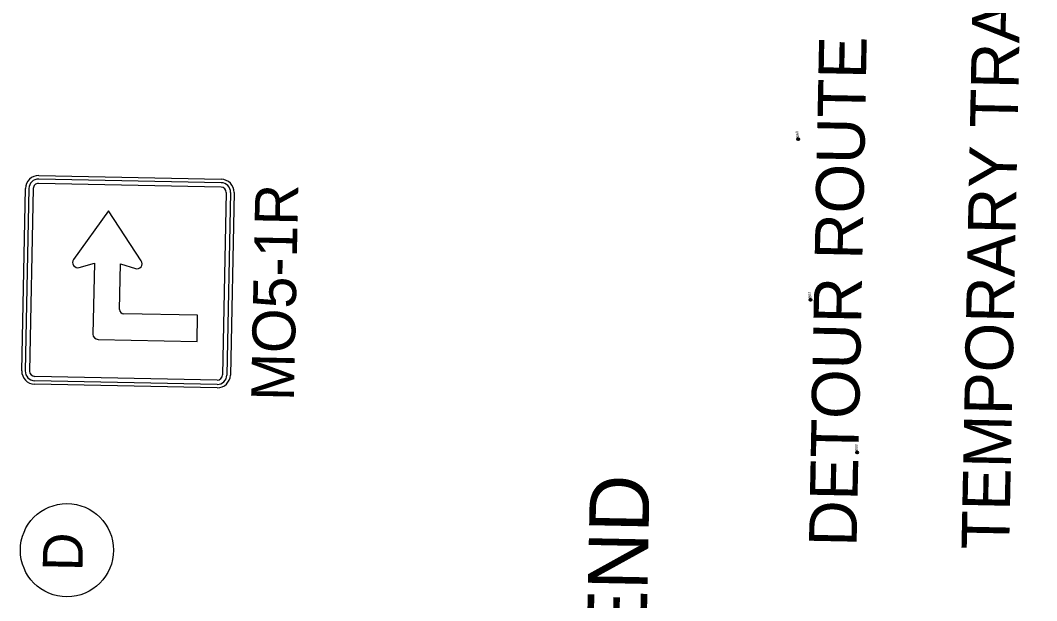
# Model space of a CAD drawing. Extents: x 335726 to 369746, y 119154 to 200788.
# Drawn here: x 356961 to 360798, y 160571 to 162762 of the extents above; entities that cross this region are included whole.
import ezdxf

# ---------------------------------------------------------------- set-up
doc = ezdxf.new("R2010")
doc.units = 0
for name, color, linetype in [('CA-TEXT', 7, 'Continuous'), ('E_SOIL_BORE1 [KAPUR_CADDS_LEVELS]', 7, 'Continuous'), ('E_SOIL_BORE2 [KAPUR_CADDS_LEVELS]', 7, 'Continuous'), ('P_MARK', 7, 'Continuous'), ('P_SGN_Cell', 7, 'Continuous')]:
    doc.layers.add(name, color=color, linetype=linetype)

msp = doc.modelspace()

# ---------------------------------------------------------------- linework, layer by layer
at = {"layer": 'CA-TEXT'}
msp.add_circle((357137.2, 160762), 175.9, dxfattribs=at)
at = {"layer": 'P_MARK'}
for p, q in [((359897.4, 162318.3), (359897.4, 162308.3)), ((359892.4, 162313.3), (359902.4, 162313.3)), ((359938.5, 161706.9), (359948.5, 161706.9)), ((359943.5, 161711.9), (359943.5, 161701.9)), ((360114.5, 161131), (360124.5, 161131)), ((360119.5, 161136), (360119.5, 161126))]:
    msp.add_line(p, q, dxfattribs=at)
for centre in [(359897.4, 162313.3), (359943.5, 161706.9), (360119.5, 161131)]:
    msp.add_circle(centre, 5, dxfattribs=at)
for centre, radius, start, end in [((359897.4, 162313.3), 4.5, 89.9869, 179.9869), ((359897.4, 162313.3), 4, 89.9869, 179.9869), ((359897.4, 162313.3), 3.5, 89.9869, 179.9869), ((359897.4, 162313.3), 3, 89.9869, 179.9869), ((359897.4, 162313.3), 2.5, 89.9869, 179.9869), ((359897.4, 162313.3), 2, 89.9869, 179.9869), ((359897.4, 162313.3), 1.5, 89.9869, 179.9869), ((359897.4, 162313.3), 1, 89.9869, 179.9869), ((359897.4, 162313.3), 0.5, 89.9869, 179.9869), ((359897.4, 162313.3), 4.5, 269.9869, 359.9869), ((359897.4, 162313.3), 4, 269.9869, 359.9869), ((359897.4, 162313.3), 3.5, 269.9869, 359.9869), ((359897.4, 162313.3), 3, 269.9869, 359.9869), ((359897.4, 162313.3), 2.5, 269.9869, 359.9869), ((359897.4, 162313.3), 2, 269.9869, 359.9869), ((359897.4, 162313.3), 1.5, 269.9869, 359.9869), ((359897.4, 162313.3), 1, 269.9869, 359.9869), ((359897.4, 162313.3), 0.5, 269.9869, 359.9869), ((359943.5, 161706.9), 4.5, 89.9869, 179.9869), ((359943.5, 161706.9), 4, 89.9869, 179.9869), ((359943.5, 161706.9), 3.5, 89.9869, 179.9869), ((359943.5, 161706.9), 3, 89.9869, 179.9869), ((359943.5, 161706.9), 2.5, 89.9869, 179.9869), ((359943.5, 161706.9), 2, 89.9869, 179.9869), ((359943.5, 161706.9), 1.5, 89.9869, 179.9869), ((359943.5, 161706.9), 1, 89.9869, 179.9869), ((359943.5, 161706.9), 0.5, 89.9869, 179.9869), ((359943.5, 161706.9), 4.5, 269.9869, 359.9869), ((359943.5, 161706.9), 4, 269.9869, 359.9869), ((359943.5, 161706.9), 3.5, 269.9869, 359.9869), ((359943.5, 161706.9), 3, 269.9869, 359.9869), ((359943.5, 161706.9), 2.5, 269.9869, 359.9869), ((359943.5, 161706.9), 2, 269.9869, 359.9869), ((359943.5, 161706.9), 1.5, 269.9869, 359.9869), ((359943.5, 161706.9), 1, 269.9869, 359.9869), ((359943.5, 161706.9), 0.5, 269.9869, 359.9869), ((360119.5, 161131), 4.5, 89.9869, 179.9869), ((360119.5, 161131), 4, 89.9869, 179.9869), ((360119.5, 161131), 3.5, 89.9869, 179.9869), ((360119.5, 161131), 3, 89.9869, 179.9869), ((360119.5, 161131), 2.5, 89.9869, 179.9869), ((360119.5, 161131), 2, 89.9869, 179.9869), ((360119.5, 161131), 1.5, 89.9869, 179.9869), ((360119.5, 161131), 1, 89.9869, 179.9869), ((360119.5, 161131), 0.5, 89.9869, 179.9869), ((360119.5, 161131), 4.5, 269.9869, 359.9869), ((360119.5, 161131), 4, 269.9869, 359.9869), ((360119.5, 161131), 3.5, 269.9869, 359.9869), ((360119.5, 161131), 3, 269.9869, 359.9869), ((360119.5, 161131), 2.5, 269.9869, 359.9869), ((360119.5, 161131), 2, 269.9869, 359.9869), ((360119.5, 161131), 1.5, 269.9869, 359.9869), ((360119.5, 161131), 1, 269.9869, 359.9869), ((360119.5, 161131), 0.5, 269.9869, 359.9869)]:
    msp.add_arc(centre, radius, start, end, dxfattribs=at)
at = {"layer": 'P_SGN_Cell'}
for p, q in [((357719.4, 162148.8), (357030.5, 162162.7)), ((357030.7, 162175.8), (357719.7, 162161.9)), ((356966.7, 161438.7), (356980.5, 162127.6)), ((356993.7, 162127.3), (356979.8, 161438.4)), ((357010.1, 162127), (356996.2, 161438.1)), ((357719.1, 162132.4), (357030.1, 162146.3)), ((357738.4, 162112.3), (357724.5, 161423.4)), ((357754.7, 162112), (357740.9, 161423.1)), ((357767.9, 162111.7), (357754, 161422.8)), ((357293.9, 162042.5), (357162.4, 161859.4)), ((357417.9, 161854.3), (357293.9, 162042.5)), ((357183.7, 161829), (357240.7, 161844.9)), ((357240.7, 161844.9), (357235.3, 161577.7)), ((357335.6, 161670.8), (357339.1, 161843)), ((357339.1, 161843), (357395.4, 161824.7)), ((357630.5, 161648.5), (357351.7, 161654.1)), ((357628.6, 161550.1), (357630.5, 161648.5)), ((357254.6, 161557.6), (357628.6, 161550.1)), ((357704.1, 161387.7), (357015.1, 161401.6)), ((357704.4, 161404.1), (357015.5, 161418)), ((357703.8, 161374.6), (357014.9, 161388.5))]:
    msp.add_line(p, q, dxfattribs=at)
for centre, radius, start, end in [((357029.7, 162126.6), 49.2, 88.8462, 178.8462), ((357029.7, 162126.6), 36.1, 88.8462, 178.8462), ((357718.7, 162112.7), 49.2, 358.8462, 88.8462), ((357029.7, 162126.6), 19.7, 88.8462, 178.8462), ((357718.7, 162112.7), 19.7, 358.8462, 88.8462), ((357718.7, 162112.7), 36.1, 358.8462, 88.8462), ((357178.4, 161847.9), 19.7, 144.3166, 285.6488), ((357401.5, 161843.4), 19.7, 252.0436, 33.3759), ((357352, 161670.5), 16.4, 178.8462, 268.8462), ((357255, 161577.3), 19.7, 178.8462, 268.8462), ((357015.9, 161437.7), 49.2, 178.8462, 268.8462), ((357015.9, 161437.7), 36.1, 178.8462, 268.8462), ((357015.9, 161437.7), 19.7, 178.8462, 268.8462), ((357704.8, 161423.8), 49.2, 268.8462, 358.8462), ((357704.8, 161423.8), 36.1, 268.8462, 358.8462), ((357704.8, 161423.8), 19.7, 268.8462, 358.8462)]:
    msp.add_arc(centre, radius, start, end, dxfattribs=at)

# ---------------------------------------------------------------- texts
at = {"layer": 'CA-TEXT'}
for s, height, p in [('TEMPORARY TRAFFIC CONTROL SIGN POST', 180, (360693.6, 160762.7)), ('DETOUR ROUTE', 180, (360117.7, 160774.3)), ('LEGEND', 225, (359312.2, 159807.3)), ('D', 150, (357195.5, 160682.1))]:
    msp.add_text(s, height=height, rotation=88.8468, dxfattribs=at).set_placement(p)
at = {"layer": 'E_SOIL_BORE1 [KAPUR_CADDS_LEVELS]'}
for s, rotation, p in [('B60', 98.5151, (359900.8, 162320.1)), ('B57', 95.5802, (359947, 161714.1))]:
    msp.add_text(s, height=10, rotation=rotation, dxfattribs=at).set_placement(p)
at = {"layer": 'E_SOIL_BORE2 [KAPUR_CADDS_LEVELS]'}
msp.add_text('B58', height=10, rotation=95.5802, dxfattribs=at).set_placement((360123.4, 161137.4))
at = {"layer": 'P_SGN_Cell'}
msp.add_text('MO5-1R', height=162, rotation=88.8462, dxfattribs=at).set_placement((357994.1, 161323.9))

doc.saveas('drawing.dxf')
